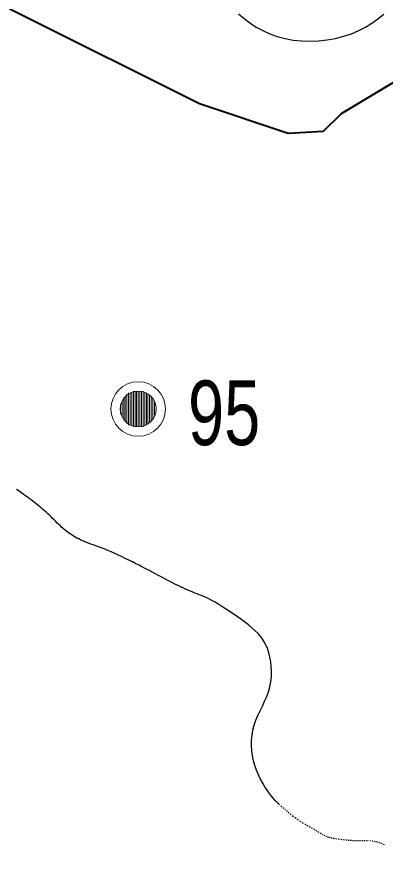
# Model space of a CAD drawing. Extents: x 553962 to 842807, y 8883888 to 9032388.
# Drawn here: x 695707 to 697984, y 8956482 to 8961682 of the extents above; entities that cross this region are included whole.
import ezdxf

# ---------------------------------------------------------------- set-up
doc = ezdxf.new("R2010")
doc.units = 0
doc.header["$LTSCALE"] = 160
for name, color, linetype, lineweight in [('15', 7, 'Continuous', 25), ('21', 7, 'Continuous', 25), ('27', 7, 'Continuous', 90), ('32', 7, 'Continuous', 13)]:
    doc.layers.add(name, color=color, linetype=linetype, lineweight=lineweight)

msp = doc.modelspace()

# ---------------------------------------------------------------- linework, layer by layer
at = {"layer": '15', "lineweight": 40}
msp.add_lwpolyline([(693487.4, 8962819.8), (696836.9, 8961144.8), (697384.1, 8960961.8), (697603.7, 8960973.6), (697714.4, 8961082.3), (698321.2, 8961447.4), (698679, 8961567.8), (700187.3, 8961472.5), (701093.5, 8961547), (704410.2, 8961560.7)], dxfattribs=at)
at = {"layer": '21'}
for p, q in [((697345.6, 8956794), (697338.8, 8956799.6)), ((697357.8, 8956783.8), (697351.9, 8956788.8)), ((697368.8, 8956774), (697363.4, 8956778.9)), ((697379.5, 8956764.3), (697374.1, 8956769.2)), ((697390.7, 8956754.3), (697385, 8956759.3)), ((697403.4, 8956743.6), (697396.8, 8956749)), ((697417.8, 8956732.3), (697410.4, 8956738)), ((697433.1, 8956720.9), (697425.3, 8956726.6)), ((697448.8, 8956709.9), (697441, 8956715.3)), ((697464.3, 8956699.8), (697456.7, 8956704.7)), ((697479.3, 8956690.6), (697471.9, 8956695)), ((697493.9, 8956682.1), (697486.7, 8956686.2)), ((697508.1, 8956674), (697501, 8956678)), ((697521.9, 8956666.1), (697515, 8956670)), ((697535.6, 8956658.2), (697528.8, 8956662.1)), ((697549, 8956650.2), (697542.3, 8956654.2)), ((697562.3, 8956642.3), (697555.7, 8956646.3)), ((697575.7, 8956634.4), (697569, 8956638.4)), ((697588.8, 8956626.7), (697582.3, 8956630.5)), ((697601.5, 8956619.5), (697595.2, 8956623)), ((697613.6, 8956613.2), (697607.7, 8956616.2)), ((697624.7, 8956608.1), (697619.3, 8956610.5)), ((697635.2, 8956604.2), (697630, 8956606)), ((697645.8, 8956601.1), (697640.4, 8956602.6)), ((697657.3, 8956598.6), (697651.4, 8956599.8)), ((697670.7, 8956596.3), (697663.7, 8956597.5)), ((697685.8, 8956594), (697678.1, 8956595.1)), ((697701.9, 8956591.7), (697693.8, 8956592.8)), ((697718.2, 8956589.7), (697710.1, 8956590.7)), ((697733.7, 8956587.9), (697726.1, 8956588.8)), ((697748.3, 8956586.4), (697741.1, 8956587.1)), ((697762.1, 8956585.1), (697755.3, 8956585.7)), ((697775.3, 8956584.2), (697768.8, 8956584.6)), ((697788.1, 8956583.5), (697781.8, 8956583.8)), ((697800.7, 8956583.1), (697794.4, 8956583.3)), ((697812.9, 8956582.8), (697806.8, 8956582.9)), ((697824.9, 8956582.7), (697818.9, 8956582.8)), ((697836.6, 8956582.6), (697830.8, 8956582.7)), ((697848, 8956582.5), (697842.3, 8956582.6)), ((697859, 8956582.4), (697853.5, 8956582.5)), ((697869.5, 8956582.3), (697864.3, 8956582.4)), ((697879.6, 8956582.2), (697874.6, 8956582.3)), ((697894, 8956581.8), (697889.2, 8956582)), ((697908.8, 8956580.5), (697903.7, 8956581.1)), ((697919.3, 8956578.7), (697914, 8956579.7)), ((697930.7, 8956576.1), (697924.9, 8956577.5)), ((697942.6, 8956572.7), (697936.6, 8956574.5)), ((697955, 8956568.4), (697948.8, 8956570.6)), ((697967.8, 8956563.3), (697961.4, 8956565.9)), ((697980.9, 8956557.4), (697974.3, 8956560.4))]:
    msp.add_line(p, q, dxfattribs=at)
for points in [[(697077.4, 8961700.9), (697111.7, 8961671.2), (697148.3, 8961643.6), (697187.3, 8961618.4), (697228.5, 8961595.8)], [(697228.5, 8961595.8), (697272, 8961576.2), (697317.5, 8961559.7), (697365.1, 8961546.7), (697414.7, 8961537.5), (697466.2, 8961532.2), (697518.9, 8961530.7), (697572.1, 8961533), (697625.2, 8961539), (697677.4, 8961548.3), (697728, 8961561), (697776.3, 8961577), (697821.6, 8961595.9), (697863.5, 8961617.8), (697902.4, 8961642.2), (697939.4, 8961668.8), (697975, 8961697.1)], [(695976.9, 8958531), (695967.2, 8958540.1), (695957.7, 8958549.4), (695948.1, 8958558.9), (695938.5, 8958568.5), (695928.9, 8958578.1), (695919.2, 8958587.8), (695909.4, 8958597.3), (695899.5, 8958606.6), (695889.5, 8958615.8), (695879.4, 8958624.8), (695869.1, 8958633.6), (695858.8, 8958642.3), (695848.4, 8958650.8), (695837.9, 8958659.2), (695827.4, 8958667.5), (695816.9, 8958675.7), (695806.4, 8958683.8), (695795.7, 8958692), (695784.8, 8958700.2), (695773.5, 8958708.6), (695761.6, 8958717.3), (695749.1, 8958726.3), (695735.9, 8958735.7), (695721.7, 8958745.6), (695706.5, 8958756)], [(696565.6, 8958234), (696553, 8958240.7), (696540.1, 8958247.5), (696526.7, 8958254.6), (696512.5, 8958262), (696497.3, 8958269.9), (696480.9, 8958278.4), (696462.9, 8958287.6), (696443.2, 8958297.7), (696422.1, 8958308.3), (696399.9, 8958319.3), (696377.1, 8958330.5), (696354, 8958341.7), (696331, 8958352.5), (696308.5, 8958362.8), (696286.8, 8958372.3), (696266.3, 8958381), (696247, 8958388.7), (696228.8, 8958395.7), (696211.6, 8958402.1), (696195.3, 8958408), (696179.9, 8958413.6), (696165.2, 8958418.8), (696151.3, 8958424), (696138, 8958429.1), (696125.3, 8958434.3), (696113, 8958439.6), (696101.2, 8958445), (696089.8, 8958450.5), (696078.8, 8958456.3), (696067.9, 8958462.3), (696057.3, 8958468.6), (696046.9, 8958475.3), (696036.5, 8958482.3), (696026.3, 8958489.6), (696016.2, 8958497.3), (696006.3, 8958505.3), (695996.4, 8958513.5), (695986.6, 8958522.1), (695976.9, 8958531)], [(697236.7, 8957815.1), (697224.9, 8957833.8), (697211.5, 8957851.4), (697196.4, 8957868.2), (697179.4, 8957884.7), (697160.2, 8957901.4), (697138.7, 8957918.7), (697114.9, 8957936.9), (697089.2, 8957955.7), (697062.3, 8957974.8), (697034.9, 8957993.6), (697007.6, 8958011.9), (696981, 8958029.1), (696955.8, 8958044.8), (696932.7, 8958058.6), (696912.1, 8958070.2), (696893.7, 8958079.8), (696877.2, 8958087.9), (696862.2, 8958094.6), (696848.2, 8958100.5), (696834.9, 8958105.8), (696821.7, 8958110.9), (696808.4, 8958116.1), (696794.5, 8958121.7), (696780.1, 8958127.8), (696765.2, 8958134.2), (696750.2, 8958141), (696734.9, 8958148), (696719.6, 8958155.2), (696704.3, 8958162.5), (696689.2, 8958169.8), (696674.4, 8958177.2), (696659.8, 8958184.6), (696645.5, 8958191.9), (696631.5, 8958199.1), (696617.8, 8958206.3), (696604.3, 8958213.4), (696591.2, 8958220.4), (696578.3, 8958227.2), (696565.6, 8958234)], [(697331.3, 8956805.9), (697323.2, 8956813.3), (697314.3, 8956822.1), (697304.5, 8956832.4), (697293.7, 8956844.7), (697281.9, 8956859.2), (697269, 8956876.1), (697255.3, 8956895.4), (697241.2, 8956916.7), (697227.2, 8956940), (697213.5, 8956965.1), (697200.6, 8956991.7), (697188.9, 8957019.6), (697178.8, 8957048.7), (697170.6, 8957078.7), (697164.4, 8957109.5), (697160.3, 8957140.9), (697158.5, 8957172.5), (697159, 8957204.3), (697161.8, 8957236), (697167.1, 8957267.4), (697175, 8957298.3), (697185.4, 8957328.5), (697197.7, 8957358.2), (697211.2, 8957387.5), (697225.2, 8957416.7), (697239.1, 8957446), (697252, 8957475.4), (697263.2, 8957505.3), (697272.1, 8957535.8), (697278.2, 8957567), (697281.4, 8957598.5), (697282.1, 8957630), (697280.5, 8957661.1), (697276.8, 8957691.2), (697271.4, 8957720), (697264.5, 8957747.1), (697256.3, 8957772.1), (697247.1, 8957794.6), (697236.7, 8957815.1)]]:
    msp.add_lwpolyline(points, dxfattribs=at)
at = {"layer": '27'}
msp.add_spline([(637260.6, 8972975.8), (641524.5, 8971056.2), (652526.1, 8965412.7), (653164.3, 8965062.8), (670790.5, 8953770.1), (686194, 8943929.9), (696283.3, 8937647.1)], degree=3, dxfattribs=at)
at = {"layer": '32'}
for p, q in [((696368, 8959325), (696368, 8959185)), ((696378, 8959335), (696378, 8959175)), ((696388, 8959345), (696388, 8959165)), ((696398, 8959355), (696398, 8959155)), ((696408, 8959355), (696408, 8959155)), ((696418, 8959355), (696418, 8959155)), ((696428, 8959365), (696428, 8959145)), ((696438, 8959365), (696438, 8959145)), ((696448, 8959365), (696448, 8959145)), ((696458, 8959365), (696458, 8959145)), ((696468, 8959365), (696468, 8959145)), ((696478, 8959365), (696478, 8959145)), ((696488, 8959365), (696488, 8959145)), ((696498, 8959355), (696498, 8959155)), ((696508, 8959355), (696508, 8959155)), ((696518, 8959345), (696518, 8959165)), ((696528, 8959335), (696528, 8959175)), ((696538, 8959325), (696538, 8959185)), ((696348, 8959285), (696348, 8959225)), ((696358, 8959305), (696358, 8959205)), ((696548, 8959315), (696548, 8959195)), ((696558, 8959295), (696558, 8959215))]:
    msp.add_line(p, q, dxfattribs=at)
for radius in [168.7, 111]:
    msp.add_circle((696458, 8959255), radius, dxfattribs=at)

# ---------------------------------------------------------------- texts
at = {"layer": '32', "width": 0.75}
msp.add_text('95', height=400, dxfattribs=at).set_placement((696765.8, 8959031.3))

doc.saveas('drawing.dxf')
